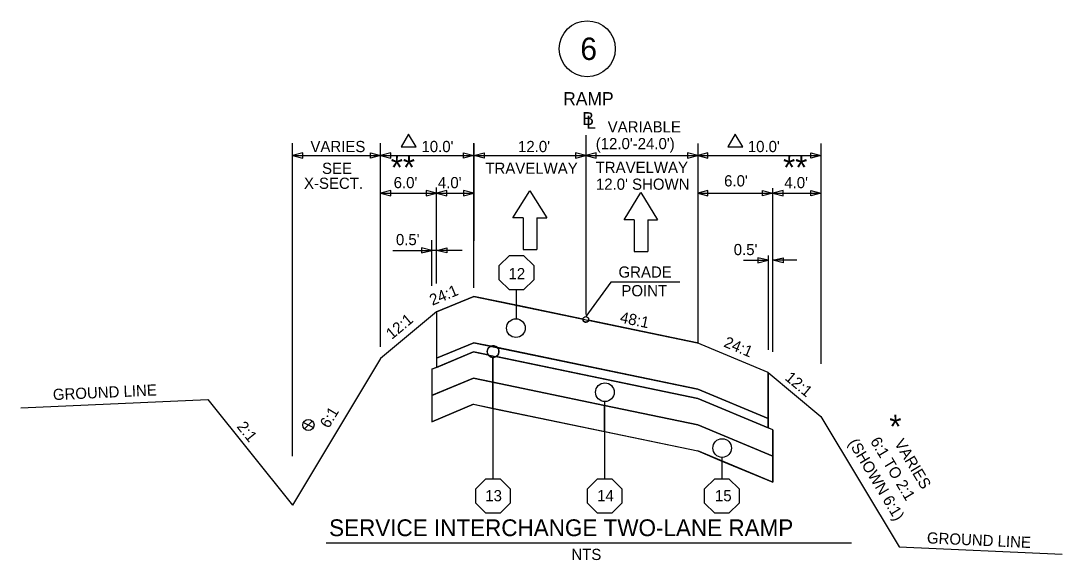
# Model space of a CAD drawing. Extents: x 4932 to 5887, y 4809 to 5473.
# Drawn here: x 5774.9 to 5886.5, y 5143.7 to 5201.5 of the extents above; entities that cross this region are included whole.
import ezdxf

# ---------------------------------------------------------------- set-up
doc = ezdxf.new("R2010")
doc.units = 0
for name, color, linetype in [('Level 2', 7, 'Continuous'), ('Level 20', 7, 'Continuous'), ('Level 25', 7, 'Continuous'), ('RD_QTY_Miscl_1', 7, 'Continuous'), ('RD_QTY_Miscl_2', 7, 'Continuous'), ('RD_QTY_Miscl_3', 7, 'Continuous'), ('RD_QTY_Miscl_4', 7, 'Continuous'), ('RD_SHT_Typical', 7, 'Continuous'), ('RD_TX_TypSect', 7, 'Continuous'), ('RD_XS_ExGround', 7, 'Continuous'), ('typical_on', 7, 'Continuous')]:
    doc.layers.add(name, color=color, linetype=linetype)

msp = doc.modelspace()

# ---------------------------------------------------------------- linework, layer by layer
at = {"layer": 'Level 2'}
for p, q in [((5819.47, 5167.31), (5819.47, 5167.31)), ((5819.47, 5167.26), (5819.47, 5167.26))]:
    msp.add_line(p, q, dxfattribs=at)
at = {"layer": 'Level 20'}
for p, q in [((5827.68, 5180.39), (5829.5, 5183.3)), ((5829.5, 5183.3), (5831.29, 5180.38)), ((5839.58, 5180.19), (5841.4, 5183.1)), ((5841.4, 5183.1), (5843.18, 5180.18)), ((5828.77, 5180.39), (5827.68, 5180.39)), ((5828.77, 5180.39), (5828.77, 5176.99)), ((5830.23, 5180.38), (5831.29, 5180.38)), ((5830.23, 5180.38), (5830.23, 5176.98)), ((5840.67, 5180.19), (5839.58, 5180.19)), ((5840.67, 5180.19), (5840.67, 5176.79)), ((5842.12, 5180.18), (5843.18, 5180.18)), ((5842.12, 5180.18), (5842.12, 5176.78)), ((5828.77, 5176.99), (5830.23, 5176.98)), ((5840.67, 5176.79), (5842.12, 5176.78))]:
    msp.add_line(p, q, dxfattribs=at)
at = {"layer": 'Level 25'}
for p, q in [((5838.16, 5173.49), (5835.49, 5169.8)), ((5845.55, 5173.49), (5838.16, 5173.49))]:
    msp.add_line(p, q, dxfattribs=at)
msp.add_circle((5835.64, 5198.52), 3, dxfattribs=at)
at = {"layer": 'RD_QTY_Miscl_1'}
for p, q in [((5823.49, 5171.97), (5819.49, 5170.3)), ((5819.47, 5170.28), (5819.47, 5165.33)), ((5847.41, 5166.99), (5835.78, 5169.41)), ((5819.47, 5165.33), (5823.49, 5167)), ((5823.49, 5167), (5825.31, 5166.63)), ((5855.04, 5163.81), (5847.41, 5166.99)), ((5826.01, 5166.48), (5847.48, 5162.01)), ((5855.04, 5158.86), (5855.04, 5163.81)), ((5847.48, 5162.01), (5855.04, 5158.86))]:
    msp.add_line(p, q, dxfattribs=at)
for points in [[(5835.19, 5169.53), (5828.06, 5171.02), (5823.49, 5171.97)], [(5819.49, 5170.3), (5819.47, 5170.29), (5819.47, 5170.28)]]:
    msp.add_lwpolyline(points, dxfattribs=at)
msp.add_circle((5827.99, 5168.57), 1, dxfattribs=at)
for centre, radius, start, end in [((5835.49, 5169.5), 0.3, 173.4555, 343.0084), ((5825.55, 5166.05), 0.63, 43.5294, 112.9344)]:
    msp.add_arc(centre, radius, start, end, dxfattribs=at)
at = {"layer": 'RD_QTY_Miscl_2'}
for p, q in [((5823.49, 5167), (5819.47, 5165.33)), ((5825.31, 5166.63), (5823.49, 5167)), ((5819.47, 5164.35), (5823.46, 5166.02)), ((5823.46, 5166.02), (5825.03, 5165.69)), ((5847.48, 5162.01), (5826.01, 5166.48)), ((5819.47, 5165.33), (5819.47, 5164.35)), ((5825.89, 5165.51), (5847.48, 5161.02)), ((5855.04, 5158.86), (5847.48, 5162.01)), ((5847.48, 5161.02), (5855.04, 5157.86)), ((5855.04, 5157.86), (5855.04, 5158.86))]:
    msp.add_line(p, q, dxfattribs=at)
for start, end in [(112.9344, 214.2796), (302.1842, 43.5294)]:
    msp.add_arc((5825.55, 5166.05), 0.63, start, end, dxfattribs=at)
at = {"layer": 'RD_QTY_Miscl_3'}
for p, q in [((5823.46, 5166.02), (5819.47, 5164.35)), ((5825.03, 5165.69), (5823.46, 5166.02)), ((5825.53, 5162.78), (5825.53, 5165.42)), ((5825.53, 5165.42), (5825.53, 5162.78)), ((5847.48, 5161.02), (5825.89, 5165.51)), ((5819.47, 5164.35), (5818.97, 5164.15)), ((5818.97, 5164.15), (5818.97, 5161.34)), ((5818.97, 5161.34), (5823.46, 5163.21)), ((5823.46, 5163.21), (5825.53, 5162.78)), ((5847.48, 5158.2), (5855.54, 5154.85)), ((5855.54, 5154.85), (5855.54, 5157.66))]:
    msp.add_line(p, q, dxfattribs=at)
for points in [[(5825.53, 5162.78), (5837.49, 5160.28), (5847.48, 5158.2)], [(5855.54, 5157.66), (5855.04, 5157.86), (5847.48, 5161.02)]]:
    msp.add_lwpolyline(points, dxfattribs=at)
msp.add_circle((5837.53, 5161.69), 1, dxfattribs=at)
for start, end in [(214.2796, 268.2692), (268.2692, 302.1842)]:
    msp.add_arc((5825.55, 5166.05), 0.63, start, end, dxfattribs=at)
at = {"layer": 'RD_QTY_Miscl_4'}
for p, q in [((5823.46, 5163.21), (5818.97, 5161.34)), ((5825.53, 5162.78), (5823.46, 5163.21)), ((5825.53, 5159.96), (5825.53, 5162.78)), ((5837.49, 5160.28), (5825.53, 5162.78)), ((5825.53, 5162.78), (5825.53, 5159.96)), ((5818.97, 5158.52), (5823.46, 5160.4)), ((5823.46, 5160.4), (5825.53, 5159.96)), ((5837.49, 5157.47), (5837.49, 5160.28)), ((5847.48, 5158.2), (5837.49, 5160.28)), ((5837.49, 5160.28), (5837.49, 5157.47)), ((5825.53, 5159.96), (5837.49, 5157.47)), ((5855.54, 5154.85), (5847.48, 5158.2)), ((5837.49, 5157.47), (5847.48, 5155.39)), ((5855.54, 5152.03), (5855.54, 5154.85))]:
    msp.add_line(p, q, dxfattribs=at)
for points in [[(5818.97, 5161.34), (5818.97, 5161.33), (5818.97, 5158.52)], [(5847.48, 5155.39), (5850.07, 5154.31), (5855.54, 5152.03)]]:
    msp.add_lwpolyline(points, dxfattribs=at)
msp.add_circle((5850.1, 5155.71), 1, dxfattribs=at)
at = {"layer": 'RD_SHT_Typical'}
for p, q in [((5819.49, 5170.3), (5823.49, 5171.97)), ((5819.49, 5170.3), (5813.49, 5165.31)), ((5819.47, 5170.29), (5819.47, 5164.35)), ((5819.47, 5165.33), (5823.49, 5167)), ((5855.04, 5163.81), (5847.41, 5166.99)), ((5823.46, 5166.02), (5818.96, 5164.14)), ((5823.46, 5166.02), (5847.48, 5161.02)), ((5813.49, 5165.31), (5804.05, 5149.57)), ((5818.97, 5164.15), (5818.97, 5158.52)), ((5855.04, 5163.81), (5860.69, 5159.1)), ((5855.04, 5163.81), (5855.04, 5157.86)), ((5823.46, 5163.21), (5818.96, 5161.33)), ((5823.46, 5163.21), (5847.48, 5158.2)), ((5855.04, 5158.86), (5847.48, 5162.01)), ((5794.96, 5160.92), (5804.05, 5149.57)), ((5823.46, 5160.4), (5818.97, 5158.52)), ((5823.46, 5160.4), (5847.48, 5155.39)), ((5855.54, 5157.66), (5847.48, 5161.02)), ((5860.69, 5159.1), (5869.07, 5145.13)), ((5855.54, 5154.85), (5847.48, 5158.2)), ((5855.54, 5157.66), (5855.54, 5152.03)), ((5855.54, 5152.03), (5847.48, 5155.39))]:
    msp.add_line(p, q, dxfattribs=at)
for points in [[(5823.49, 5171.97), (5847.41, 5166.99)], [(5823.49, 5167), (5847.48, 5162.01)]]:
    msp.add_lwpolyline(points, dxfattribs=at)
at = {"layer": 'RD_TX_TypSect'}
for p, q in [((5835.48, 5189.24), (5835.48, 5170.02)), ((5804.05, 5154.85), (5804.05, 5188.4)), ((5813.49, 5166.55), (5813.49, 5188.4)), ((5823.49, 5172.88), (5823.49, 5188.4)), ((5823.49, 5188.37), (5823.49, 5177.91)), ((5847.48, 5188.37), (5847.48, 5166.97)), ((5860.69, 5188.37), (5860.69, 5164.72)), ((5804.05, 5187.08), (5813.49, 5187.08)), ((5813.49, 5187.08), (5823.49, 5187.08)), ((5823.49, 5187.08), (5835.48, 5187.08)), ((5835.48, 5187.08), (5847.48, 5187.08)), ((5847.48, 5187.08), (5860.69, 5187.08)), ((5819.49, 5173.34), (5819.49, 5183.66)), ((5855.54, 5166.02), (5855.54, 5183.57)), ((5813.49, 5183.04), (5819.49, 5183.04)), ((5819.49, 5183.04), (5823.49, 5183.04)), ((5847.48, 5183.04), (5855.54, 5183.04)), ((5855.54, 5183.04), (5860.69, 5183.04)), ((5818.99, 5173.11), (5818.99, 5177.98)), ((5814.81, 5176.9), (5818.99, 5176.9)), ((5822.25, 5176.9), (5818.99, 5176.9)), ((5852.38, 5175.84), (5855.04, 5175.84)), ((5855.04, 5176.37), (5855.04, 5166.22)), ((5858.11, 5175.84), (5855.54, 5175.84)), ((5828.06, 5169.57), (5828.06, 5172.67)), ((5825.53, 5165.42), (5825.53, 5152.4)), ((5837.49, 5160.69), (5837.49, 5152.4)), ((5805.22, 5158.45), (5806.29, 5157.9)), ((5805.34, 5157.75), (5806.17, 5158.6)), ((5850.07, 5154.71), (5850.07, 5152.4)), ((5807.64, 5145.55), (5863.95, 5145.55))]:
    msp.add_line(p, q, dxfattribs=at)
for points in [[(5816.49, 5189.37), (5815.69, 5187.99), (5817.29, 5187.99)], [(5851.5, 5189.37), (5850.7, 5187.99), (5852.3, 5187.99)], [(5805.15, 5186.8), (5805.15, 5187.35), (5804.05, 5187.08)], [(5812.39, 5186.8), (5812.39, 5187.35), (5813.49, 5187.08)], [(5814.59, 5186.8), (5814.59, 5187.35), (5813.49, 5187.08)], [(5822.38, 5186.8), (5822.38, 5187.35), (5823.49, 5187.08)], [(5824.59, 5187.35), (5824.59, 5186.8), (5823.49, 5187.08)], [(5834.38, 5187.35), (5834.38, 5186.8), (5835.48, 5187.08)], [(5836.59, 5186.8), (5836.59, 5187.35), (5835.48, 5187.08)], [(5846.37, 5187.35), (5846.37, 5186.8), (5847.48, 5187.08)], [(5848.58, 5186.8), (5848.58, 5187.35), (5847.48, 5187.08)], [(5859.59, 5186.8), (5859.59, 5187.35), (5860.69, 5187.08)], [(5814.59, 5182.76), (5814.59, 5183.31), (5813.49, 5183.04)], [(5818.39, 5183.31), (5818.39, 5182.76), (5819.49, 5183.04)], [(5820.59, 5182.76), (5820.59, 5183.31), (5819.49, 5183.04)], [(5822.38, 5183.31), (5822.38, 5182.76), (5823.49, 5183.04)], [(5848.58, 5182.76), (5848.58, 5183.31), (5847.48, 5183.04)], [(5854.43, 5182.76), (5854.43, 5183.31), (5855.54, 5183.04)], [(5856.64, 5182.76), (5856.64, 5183.31), (5855.54, 5183.04)], [(5859.59, 5182.76), (5859.59, 5183.31), (5860.69, 5183.04)], [(5817.89, 5177.18), (5817.89, 5176.63), (5818.99, 5176.9)], [(5820.59, 5177.18), (5820.59, 5176.63), (5819.49, 5176.9)], [(5853.93, 5176.11), (5853.93, 5175.56), (5855.04, 5175.84)], [(5856.64, 5176.11), (5856.64, 5175.56), (5855.54, 5175.84)]]:
    msp.add_lwpolyline(points, close=True, dxfattribs=at)
for centre, radius in [((5827.99, 5168.57), 1), ((5835.49, 5169.5), 0.3), ((5825.55, 5166.05), 0.63), ((5837.53, 5161.69), 1), ((5805.76, 5158.18), 0.6), ((5850.1, 5155.71), 1)]:
    msp.add_circle(centre, radius, dxfattribs=at)
at = {"layer": 'RD_XS_ExGround'}
for p, q in [((5774.93, 5160.01), (5794.96, 5160.92)), ((5869.07, 5145.13), (5886.54, 5144.34))]:
    msp.add_line(p, q, dxfattribs=at)
at = {"layer": 'typical_on'}
for points in [[(5829.9, 5175.28), (5829.9, 5173.76), (5828.82, 5172.67), (5827.29, 5172.67), (5826.21, 5173.76), (5826.21, 5175.28), (5827.29, 5176.37), (5828.82, 5176.37)], [(5827.38, 5151.32), (5827.38, 5149.79), (5826.3, 5148.71), (5824.77, 5148.71), (5823.69, 5149.79), (5823.69, 5151.32), (5824.77, 5152.4), (5826.3, 5152.4)], [(5839.34, 5151.32), (5839.34, 5149.79), (5838.26, 5148.71), (5836.73, 5148.71), (5835.65, 5149.79), (5835.65, 5151.32), (5836.73, 5152.4), (5838.26, 5152.4)], [(5851.91, 5151.32), (5851.91, 5149.79), (5850.83, 5148.71), (5849.3, 5148.71), (5848.22, 5149.79), (5848.22, 5151.32), (5849.3, 5152.4), (5850.83, 5152.4)]]:
    msp.add_lwpolyline(points, close=True, dxfattribs=at)

# ---------------------------------------------------------------- texts
at = {"layer": 'Level 25'}
msp.add_text('6', height=2.4, dxfattribs=at).set_placement((5834.9, 5197.32))
at = {"layer": 'RD_TX_TypSect'}
for s, height, p in [('RAMP', 1.4, (5833.06, 5192.47)), ('B ', 1.4, (5835.11, 5190.33)), ('L', 1.4, (5835.52, 5189.94)), ('VARIES', 1.2, (5805.97, 5187.44)), ("10.0'", 1.2, (5817.87, 5187.44)), ("12.0'", 1.2, (5828.22, 5187.44)), ("10.0'", 1.2, (5852.85, 5187.44)), ('**', 2.5, (5814.58, 5184.55)), ('**', 2.5, (5856.63, 5184.55)), ('SEE', 1.2, (5807.21, 5185.1)), ('TRAVELWAY', 1.2, (5824.72, 5185.11)), ('X-SECT.', 1.2, (5805.28, 5183.5)), ("6.0'", 1.2, (5814.89, 5183.57)), ("4.0'", 1.2, (5819.63, 5183.57)), ("6.0'", 1.2, (5850.31, 5183.76)), ("4.0'", 1.2, (5856.76, 5183.57)), ("0.5'", 1.2, (5815.13, 5177.46)), ("0.5'", 1.2, (5851.34, 5176.39)), ('12', 1.2, (5827.2, 5173.81)), ('GRADE', 1.2, (5838.99, 5173.98)), ('POINT', 1.2, (5839.3, 5171.98)), ('*', 2.5, (5868.02, 5156.77)), ('13', 1.2, (5824.71, 5150)), ('14', 1.2, (5836.7, 5150)), ('15', 1.2, (5849.33, 5150)), ('SERVICE INTERCHANGE TWO-LANE RAMP', 1.8, (5807.97, 5146.26)), ('NTS', 1.2, (5833.94, 5143.7))]:
    msp.add_text(s, height=height, dxfattribs=at).set_placement(p)
for s, rotation, p in [('VARIABLE', 0.0016, (5837.83, 5189.55)), ("(12.0'-24.0')", 0.0016, (5836.55, 5187.75)), ('TRAVELWAY', 0.0016, (5836.54, 5185.2)), ("12.0' SHOWN", 0.0016, (5836.57, 5183.4)), ('24:1', 22.619, (5819.04, 5170.96)), ('48:1', 348.2317, (5839.08, 5169.18)), ('12:1', 39.8056, (5814.69, 5167.3)), ('24:1', 337.3801, (5850.18, 5166.61)), ('12:1', 320.1939, (5856.74, 5163.1)), ('GROUND LINE', 2.6095, (5778.39, 5160.84)), ('6:1', 59.0362, (5807.93, 5157.74)), ('2:1', 308.6598, (5798.02, 5157.98)), ('6:1 TO 2:1', 300.9638, (5865.93, 5156.44)), ('VARIES', 300.9638, (5868.51, 5156.23)), ('(SHOWN 6:1)', 300.9638, (5863.58, 5156.28)), ('GROUND LINE', 357.3905, (5872.03, 5145.49))]:
    msp.add_text(s, height=1.2, rotation=rotation, dxfattribs=at).set_placement(p)

doc.saveas('drawing.dxf')
